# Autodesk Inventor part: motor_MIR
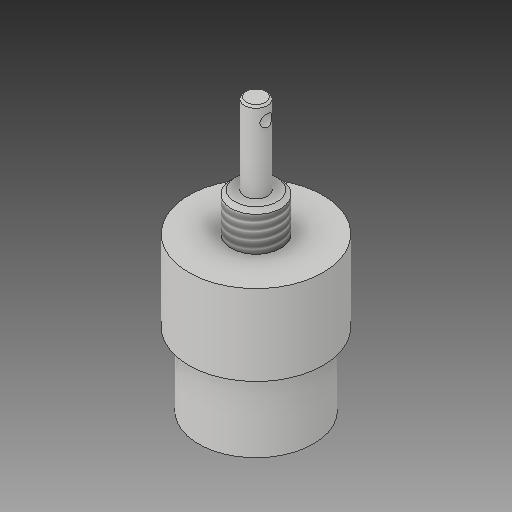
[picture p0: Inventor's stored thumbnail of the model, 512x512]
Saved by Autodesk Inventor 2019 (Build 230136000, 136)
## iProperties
Created: 2019-10
Part Number: motor_MIR
Material: Generic
Document SubType Name: Modeling
Designer: PRADYUMNA
Density: 1 g/cm^3
Appearance: Default
Author: Asus
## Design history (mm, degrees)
derived "motor.ipt"
  sketch "Sketch1"
    geometry: C1 r 6.5 at (0, 0) reference; 1 further point
  sketch "Sketch2"
    geometry: 1 further point
  sketch "Sketch3"
    geometry: C1 r 17.5 at (0, 0) reference; 1 further point
  sketch "Sketch4"
    geometry: C1 r 15 at (0, 0) reference; 1 further point
  sketch "Sketch5"
    geometry: C1 r 3 at (0, 0) reference; 1 further point
  sketch "Sketch6"
    geometry: C1 r 1.55 at (-27.143, 0) reference; 1 further point
  sketch "Sketch7"
    geometry: L1 (-12.192, 2.12)-(-11.485, 2.12) reference; L2 (-11.485, 2.12)-(-11.485, -2.356) reference; L3 (-11.485, -2.356)-(-12.192, -2.356) reference; L4 (-12.192, -2.356)-(-12.192, 2.12) reference; L5 (11.603, 2.12)-(12.546, 2.12) reference; L6 (12.546, 2.12)-(12.546, -2.356) reference; L7 (12.546, -2.356)-(11.603, -2.356) reference; L8 (11.603, -2.356)-(11.603, 2.12) reference; 1 further point
feature "Solid1::motor.ipt"
tag "TaggingFeature1"
body "Solid1"
